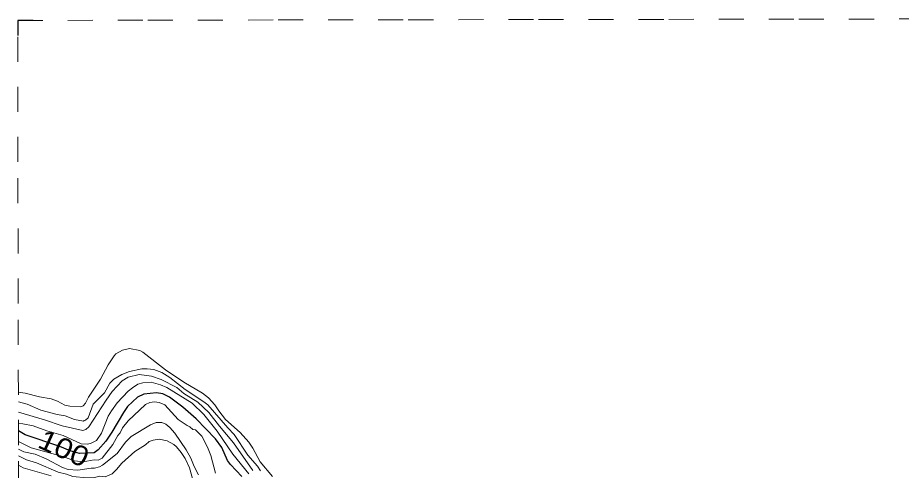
# Model space of a CAD drawing. Extents: x 474.5 to 500, y 7345.7 to 7373.4.
# Drawn here: x 474.522 to 478.051, y 7371.599 to 7373.405 of the extents above; entities that cross this region are included whole.
import ezdxf
from ezdxf.enums import TextEntityAlignment as Align

# ---------------------------------------------------------------- set-up
doc = ezdxf.new("R2010")
doc.units = 0
doc.header["$LTSCALE"] = 0.032
doc.linetypes.add('SHORT_DASHED', pattern=[2.7, 1.5, -1.2])
for name, color, linetype, lineweight in [('1', 7, 'Continuous', 25), ('2', 7, 'Continuous', 13), ('22', 7, 'SHORT_DASHED', 13), ('63', 7, 'Continuous', 25)]:
    doc.layers.add(name, color=color, linetype=linetype, lineweight=lineweight)
doc.layers.add('61', color=7, linetype='Continuous')

msp = doc.modelspace()

# ---------------------------------------------------------------- linework, layer by layer
at = {"layer": '1'}
for points in [[(475.0769, 7371.9083), (475.0257, 7371.9027), (475.0001, 7371.8908), (474.9611, 7371.8537), (474.9447, 7371.8301), (474.8981, 7371.7507), (474.8742, 7371.7156), (474.8443, 7371.6808), (474.8283, 7371.6683), (474.7692, 7371.6659), (474.7318, 7371.6766), (474.6902, 7371.6943), (474.552, 7371.7399), (474.5251, 7371.7562)], [(475.4175, 7371.5747), (475.3715, 7371.6222), (475.3602, 7371.6381), (475.3375, 7371.6898), (475.3117, 7371.7244), (475.2352, 7371.804), (475.1822, 7371.8515), (475.1291, 7371.8902), (475.102, 7371.9044), (475.0769, 7371.9083)]]:
    msp.add_lwpolyline(points, dxfattribs=at)
at = {"layer": '2'}
for points in [[(475.5402, 7371.5742), (475.4906, 7371.6326), (475.4608, 7371.6874), (475.4449, 7371.7109), (475.4113, 7371.7492), (475.3519, 7371.8021), (475.3249, 7371.836), (475.3098, 7371.8603), (475.2842, 7371.8875), (475.2603, 7371.9062), (475.1852, 7371.9511), (475.1127, 7371.9999), (475.0226, 7372.0702), (475.0096, 7372.0767), (474.9688, 7372.0845), (474.9403, 7372.078), (474.914, 7372.0631), (474.9069, 7372.0561), (474.8831, 7372.0205), (474.8528, 7371.9631), (474.8045, 7371.8906), (474.7926, 7371.867), (474.7831, 7371.8566), (474.7749, 7371.8517), (474.7299, 7371.855), (474.7111, 7371.859), (474.6815, 7371.8749), (474.6554, 7371.8844), (474.6089, 7371.8917), (474.5522, 7371.9074), (474.5248, 7371.9112)], [(474.5249, 7371.872), (474.5595, 7371.863), (474.615, 7371.8391), (474.6802, 7371.822), (474.7113, 7371.8166), (474.7486, 7371.8013), (474.7848, 7371.7952), (474.7877, 7371.7981), (474.7927, 7371.7985), (474.8031, 7371.8089), (474.8234, 7371.8633), (474.8694, 7371.9076), (474.8898, 7371.9464), (474.9059, 7371.9626), (474.9378, 7371.9817), (474.9688, 7371.9935), (475.0174, 7372.0041), (475.0396, 7372.0042), (475.0658, 7372.0009), (475.0977, 7371.9888), (475.1293, 7371.969), (475.1912, 7371.9208), (475.2657, 7371.8726), (475.2811, 7371.8603), (475.3616, 7371.7678), (475.3873, 7371.7413), (475.4417, 7371.6599), (475.4803, 7371.6152), (475.4922, 7371.5974)], [(475.461, 7371.5975), (475.3846, 7371.7089), (475.3275, 7371.7745), (475.2858, 7371.83), (475.2417, 7371.8711), (475.1861, 7371.9049), (475.1581, 7371.929), (475.0947, 7371.9616), (475.0564, 7371.9744), (475.0079, 7371.981), (474.9628, 7371.971), (474.9392, 7371.956), (474.8999, 7371.9133), (474.8755, 7371.8794), (474.8062, 7371.772), (474.7946, 7371.7618), (474.783, 7371.7578), (474.6996, 7371.7761), (474.6297, 7371.7999), (474.525, 7371.8309)], [(474.525, 7371.7858), (474.543, 7371.7845), (474.5839, 7371.7767), (474.6393, 7371.7561), (474.7034, 7371.7376), (474.7762, 7371.7046), (474.8003, 7371.7039), (474.8124, 7371.706), (474.8372, 7371.7185), (474.8573, 7371.7475), (474.8839, 7371.8148), (474.8965, 7371.8368), (474.9192, 7371.8685), (474.9637, 7371.9151), (474.9803, 7371.9286), (475.0026, 7371.9422), (475.0214, 7371.9483), (475.0552, 7371.9507), (475.0926, 7371.9402), (475.1182, 7371.9299), (475.2195, 7371.8669), (475.2651, 7371.822), (475.3183, 7371.7552), (475.3818, 7371.6637), (475.4449, 7371.585)], [(475.3124, 7371.5875), (475.2929, 7371.6576), (475.2806, 7371.6919), (475.2571, 7371.7358), (475.2328, 7371.7605), (475.2218, 7371.7617), (475.2102, 7371.7725), (475.1986, 7371.7773), (475.1626, 7371.8016), (475.1093, 7371.8597), (475.0878, 7371.8692), (475.0682, 7371.8716), (475.0498, 7371.8693), (475.0332, 7371.8614), (474.9629, 7371.797), (474.941, 7371.7687), (474.9314, 7371.7489), (474.9226, 7371.7382), (474.9026, 7371.7023), (474.8593, 7371.648), (474.8439, 7371.6389), (474.8274, 7371.6411), (474.7837, 7371.6324), (474.7488, 7371.6372), (474.7028, 7371.6539), (474.5759, 7371.6889), (474.5252, 7371.7144)], [(474.5252, 7371.6827), (474.5467, 7371.6723), (474.5922, 7371.6632), (474.6366, 7371.6442), (474.7012, 7371.6095), (474.7234, 7371.6022), (474.7629, 7371.5989), (474.816, 7371.6076), (474.8287, 7371.6078), (474.8485, 7371.6134), (474.8607, 7371.62), (474.9199, 7371.6657), (474.9524, 7371.7107), (474.9751, 7371.7334), (475.0525, 7371.7798), (475.0751, 7371.7895), (475.0974, 7371.7895), (475.1144, 7371.783), (475.1297, 7371.77), (475.1497, 7371.7472), (475.1946, 7371.6805), (475.2137, 7371.647), (475.2273, 7371.6135), (475.2447, 7371.5803)], [(475.1755, 7371.6706), (475.1571, 7371.693), (475.1452, 7371.7025), (475.1195, 7371.717), (475.0878, 7371.7232), (475.0637, 7371.7193), (475.0467, 7371.7135), (475.0325, 7371.7), (474.9901, 7371.6734), (474.9381, 7371.6277), (474.917, 7371.6018), (474.8999, 7371.585), (474.8722, 7371.5726), (474.8497, 7371.575), (474.8284, 7371.57), (474.7965, 7371.5686), (474.7425, 7371.5739), (474.7171, 7371.5838), (474.6844, 7371.5921), (474.5978, 7371.6292), (474.5573, 7371.6407), (474.5253, 7371.6564)], [(475.2267, 7371.5425), (475.2079, 7371.6091), (475.1906, 7371.6454), (475.1755, 7371.6706)], [(474.5253, 7371.6193), (474.5448, 7371.6094), (474.6565, 7371.5767)]]:
    msp.add_lwpolyline(points, dxfattribs=at)
at = {"layer": '22'}
for points in [[(474.5222, 7373.3943), (475.0421, 7373.3952), (475.5621, 7373.3961), (476.0821, 7373.397), (476.602, 7373.3978), (477.122, 7373.3987), (477.6419, 7373.3995), (478.1619, 7373.4003), (478.6818, 7373.401), (479.2018, 7373.4018), (479.7217, 7373.4025), (480.2417, 7373.4032), (480.7617, 7373.4039), (481.2816, 7373.4046), (481.8016, 7373.4053)], [(474.5381, 7364.3565), (474.5371, 7364.9213), (474.5361, 7365.4862), (474.5351, 7366.0511), (474.5341, 7366.616), (474.5331, 7367.1808), (474.5321, 7367.7457), (474.5311, 7368.3105), (474.5301, 7368.8754), (474.5291, 7369.4403), (474.5281, 7370.0051), (474.5272, 7370.57), (474.5262, 7371.1349), (474.5252, 7371.6997), (474.5242, 7372.2646), (474.5232, 7372.8295), (474.5222, 7373.3943)]]:
    msp.add_lwpolyline(points, dxfattribs=at)
at = {"layer": '63'}
msp.add_lwpolyline([(474.5838, 7373.3943), (474.5222, 7373.3943), (474.5222, 7373.3336)], dxfattribs=at)

# ---------------------------------------------------------------- texts
at = {"layer": '61', "width": 1.15}
msp.add_text('100', height=0.08, rotation=335.595, dxfattribs=at).set_placement((474.6901, 7371.6504), align=Align.CENTER)

doc.saveas('drawing.dxf')
